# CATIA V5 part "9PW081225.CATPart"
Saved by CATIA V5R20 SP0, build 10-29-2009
Part number: 9PW081225
Revision: ANY
Definition: UNKNOWN
Nomenclature: 9PW081225
Source: Unknown
Bounding box of the stored display mesh (mm): x -139.516 to 0, y -11.973 to 4, z -6.1 to 6.1
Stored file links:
  C:\Users\Utente\Desktop\IO LAVORO\3D X SITO CF\CUMSA\3D files PW\pw081225\pw081225_ejection\9PW081225.CATPart
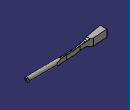
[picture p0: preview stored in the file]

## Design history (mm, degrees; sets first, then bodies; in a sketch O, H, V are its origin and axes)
Body1 "Chaflán3" (main body)
  Solid1: solid without history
